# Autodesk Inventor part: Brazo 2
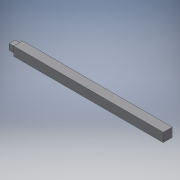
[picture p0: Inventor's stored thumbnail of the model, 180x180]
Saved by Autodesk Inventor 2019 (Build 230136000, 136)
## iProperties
Created: 2019-02
Part Number: Brazo 2
Material: Genérico
Document SubType Name: Modeling
Designer: Juan Manuel Montalvo Navarrete
Density: 1 g/cm^3
Appearance: Valor por defecto
Author: Juan Manuel Montalvo Navarrete
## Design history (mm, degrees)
sketch "Boceto1"
  geometry: L1 (-10, 10)-(10, 10); L2 (10, 10)-(10, -10); L3 (10, -10)-(-10, -10); L4 (-10, -10)-(-10, 10); L5 (-10, 10)-(10, -10); L6 (10, 10)-(-10, -10); 1 further point
  constraints: 12 end point, 2 midpoint, 2 parallel, 1 horizontal, 1 perpendicular
  dimensions: "d0" = 20 distance of L2.end L3.end; "d1" = 20 distance of L1.end L2.end
extrude "Extrusión1" new body sketch "Boceto1" distance "d2" = 520; taper "d3" = 0 deg
sketch "Sketch2"
  geometry: L1 (-15, -15)-(15, -15); L2 (15, -15)-(15, 15); L3 (15, 15)-(-15, 15); L4 (-15, 15)-(-15, -15); L5 (-15, -15)-(15, 15); L6 (15, -15)-(-15, 15); 1 further point
  constraints: 12 end point, 2 midpoint, 2 parallel, 1 horizontal, 1 perpendicular
  dimensions: "d4" = 30 distance of L3.end L2.end; "d5" = 30 distance of L2.end L1.end
extrude "Extrusion2" join sketch "Sketch2" distance "d6" = 490; taper "d7" = 0 deg
node "Sólido1"
